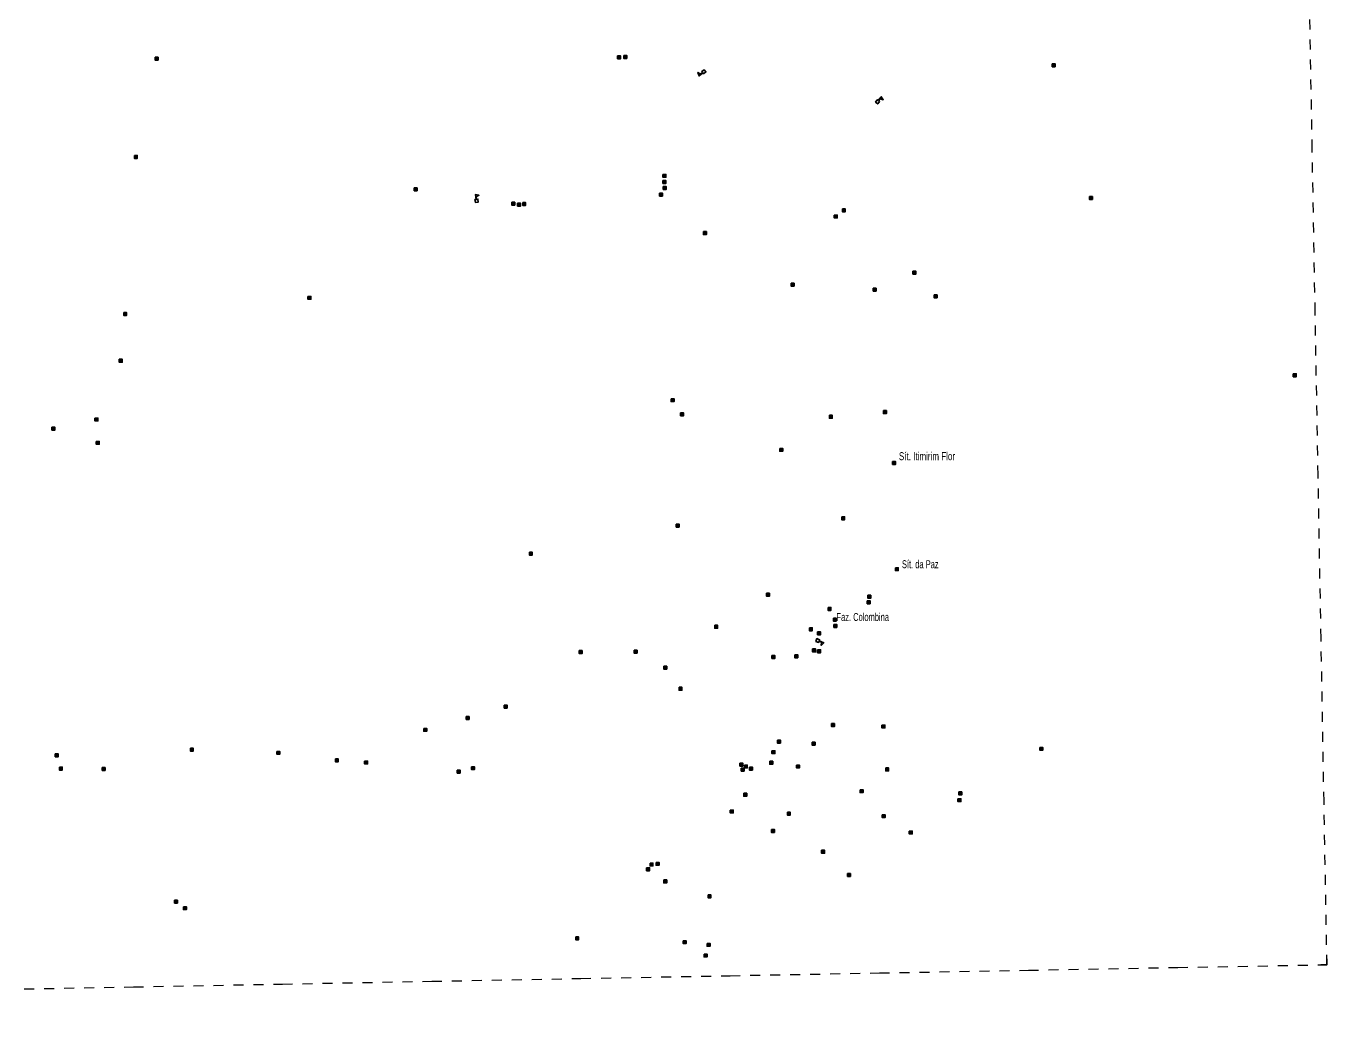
# Model space of a CAD drawing. Extents: x 220.8 to 246.7, y 7287.6 to 7315.8.
# Drawn here: x 233.65 to 246.65, y 7287.6 to 7297.47 of the extents above; entities that cross this region are included whole.
import ezdxf

# ---------------------------------------------------------------- set-up
doc = ezdxf.new("R2010")
doc.units = 0
doc.header["$LTSCALE"] = 0.032
doc.linetypes.add('SHORT_DASHED', pattern=[2.7, 1.5, -1.2])
for name, color, linetype, lineweight in [('2', 7, 'Continuous', 25), ('4', 7, 'Continuous', 25), ('58', 7, 'SHORT_DASHED', 13), ('63', 7, 'Continuous', 25)]:
    doc.layers.add(name, color=color, linetype=linetype, lineweight=lineweight)
doc.layers.add('61', color=7, linetype='Continuous')

msp = doc.modelspace()

# ---------------------------------------------------------------- hatches: boundary and pattern name
at = {"layer": '2'}
for points in [[(234.9398, 7297.1548), (234.9688, 7297.1548), (234.9688, 7297.1258), (234.9398, 7297.1258)], [(239.5615, 7297.1681), (239.5905, 7297.1681), (239.5905, 7297.1391), (239.5615, 7297.1391)], [(239.6233, 7297.1722), (239.6523, 7297.1722), (239.6523, 7297.1432), (239.6233, 7297.1432)], [(243.9053, 7297.089), (243.9343, 7297.089), (243.9343, 7297.06), (243.9053, 7297.06)], [(234.7328, 7296.1724), (234.7618, 7296.1724), (234.7618, 7296.1434), (234.7328, 7296.1434)], [(240.0151, 7295.9833), (240.0441, 7295.9833), (240.0441, 7295.9543), (240.0151, 7295.9543)], [(240.0151, 7295.9221), (240.0441, 7295.9221), (240.0441, 7295.8931), (240.0151, 7295.8931)], [(237.5286, 7295.8492), (237.5576, 7295.8492), (237.5576, 7295.8202), (237.5286, 7295.8202)], [(239.9811, 7295.7962), (240.0101, 7295.7962), (240.0101, 7295.7672), (239.9811, 7295.7672)], [(240.0183, 7295.862), (240.0473, 7295.862), (240.0473, 7295.833), (240.0183, 7295.833)], [(238.5044, 7295.7059), (238.5334, 7295.7059), (238.5334, 7295.6769), (238.5044, 7295.6769)], [(238.5624, 7295.6956), (238.5914, 7295.6956), (238.5914, 7295.6666), (238.5624, 7295.6666)], [(238.6136, 7295.7025), (238.6426, 7295.7025), (238.6426, 7295.6735), (238.6136, 7295.6735)], [(244.2773, 7295.7623), (244.3063, 7295.7623), (244.3063, 7295.7333), (244.2773, 7295.7333)], [(241.7269, 7295.5771), (241.7559, 7295.5771), (241.7559, 7295.5481), (241.7269, 7295.5481)], [(241.8083, 7295.639), (241.8373, 7295.639), (241.8373, 7295.61), (241.8083, 7295.61)], [(240.4198, 7295.4118), (240.4488, 7295.4118), (240.4488, 7295.3828), (240.4198, 7295.3828)], [(242.5135, 7295.0161), (242.5425, 7295.0161), (242.5425, 7294.9871), (242.5135, 7294.9871)], [(241.2955, 7294.8965), (241.3245, 7294.8965), (241.3245, 7294.8675), (241.2955, 7294.8675)], [(236.4668, 7294.7641), (236.4958, 7294.7641), (236.4958, 7294.7351), (236.4668, 7294.7351)], [(242.1163, 7294.8463), (242.1453, 7294.8463), (242.1453, 7294.8173), (242.1163, 7294.8173)], [(242.7249, 7294.7791), (242.7539, 7294.7791), (242.7539, 7294.7501), (242.7249, 7294.7501)], [(234.6258, 7294.6031), (234.6548, 7294.6031), (234.6548, 7294.5741), (234.6258, 7294.5741)], [(234.5814, 7294.1357), (234.6104, 7294.1357), (234.6104, 7294.1067), (234.5814, 7294.1067)], [(246.3141, 7293.9909), (246.3431, 7293.9909), (246.3431, 7293.9619), (246.3141, 7293.9619)], [(240.0965, 7293.7422), (240.1255, 7293.7422), (240.1255, 7293.7132), (240.0965, 7293.7132)], [(240.1913, 7293.6007), (240.2203, 7293.6007), (240.2203, 7293.5717), (240.1913, 7293.5717)], [(242.2183, 7293.6225), (242.2473, 7293.6225), (242.2473, 7293.5935), (242.2183, 7293.5935)], [(233.9084, 7293.4575), (233.9374, 7293.4575), (233.9374, 7293.4285), (233.9084, 7293.4285)], [(234.3386, 7293.5484), (234.3676, 7293.5484), (234.3676, 7293.5194), (234.3386, 7293.5194)], [(241.6782, 7293.5763), (241.7072, 7293.5763), (241.7072, 7293.5473), (241.6782, 7293.5473)], [(234.352, 7293.3155), (234.381, 7293.3155), (234.381, 7293.2865), (234.352, 7293.2865)], [(241.1827, 7293.2455), (241.2117, 7293.2455), (241.2117, 7293.2165), (241.1827, 7293.2165)], [(242.3099, 7293.1141), (242.3389, 7293.1141), (242.3389, 7293.0851), (242.3099, 7293.0851)], [(241.801, 7292.5617), (241.83, 7292.5617), (241.83, 7292.5327), (241.801, 7292.5327)], [(240.1468, 7292.4885), (240.1758, 7292.4885), (240.1758, 7292.4595), (240.1468, 7292.4595)], [(238.6794, 7292.2077), (238.7084, 7292.2077), (238.7084, 7292.1787), (238.6794, 7292.1787)], [(242.3372, 7292.0526), (242.3662, 7292.0526), (242.3662, 7292.0236), (242.3372, 7292.0236)], [(241.0504, 7291.7971), (241.0794, 7291.7971), (241.0794, 7291.7681), (241.0504, 7291.7681)], [(242.0629, 7291.7774), (242.0919, 7291.7774), (242.0919, 7291.7484), (242.0629, 7291.7484)], [(241.6643, 7291.656), (241.6933, 7291.656), (241.6933, 7291.627), (241.6643, 7291.627)], [(242.0563, 7291.7223), (242.0853, 7291.7223), (242.0853, 7291.6933), (242.0563, 7291.6933)], [(241.7182, 7291.5482), (241.7472, 7291.5482), (241.7472, 7291.5192), (241.7182, 7291.5192)], [(240.5318, 7291.4777), (240.5608, 7291.4777), (240.5608, 7291.4487), (240.5318, 7291.4487)], [(241.4776, 7291.4528), (241.5066, 7291.4528), (241.5066, 7291.4238), (241.4776, 7291.4238)], [(241.5606, 7291.4113), (241.5896, 7291.4113), (241.5896, 7291.3823), (241.5606, 7291.3823)], [(241.7224, 7291.486), (241.7514, 7291.486), (241.7514, 7291.457), (241.7224, 7291.457)], [(241.5108, 7291.2412), (241.5398, 7291.2412), (241.5398, 7291.2122), (241.5108, 7291.2122)], [(239.1778, 7291.2247), (239.2068, 7291.2247), (239.2068, 7291.1957), (239.1778, 7291.1957)], [(239.7265, 7291.2284), (239.7555, 7291.2284), (239.7555, 7291.1994), (239.7265, 7291.1994)], [(241.1043, 7291.1748), (241.1333, 7291.1748), (241.1333, 7291.1458), (241.1043, 7291.1458)], [(241.3324, 7291.1831), (241.3614, 7291.1831), (241.3614, 7291.1541), (241.3324, 7291.1541)], [(241.5606, 7291.2329), (241.5896, 7291.2329), (241.5896, 7291.2039), (241.5606, 7291.2039)], [(240.023, 7291.069), (240.052, 7291.069), (240.052, 7291.04), (240.023, 7291.04)], [(240.1751, 7290.8577), (240.2041, 7290.8577), (240.2041, 7290.8287), (240.1751, 7290.8287)], [(238.4279, 7290.6801), (238.4569, 7290.6801), (238.4569, 7290.6511), (238.4279, 7290.6511)], [(238.0488, 7290.5659), (238.0778, 7290.5659), (238.0778, 7290.5369), (238.0488, 7290.5369)], [(241.6991, 7290.4949), (241.7281, 7290.4949), (241.7281, 7290.4659), (241.6991, 7290.4659)], [(242.2036, 7290.4808), (242.2326, 7290.4808), (242.2326, 7290.4518), (242.2036, 7290.4518)], [(237.6247, 7290.4477), (237.6537, 7290.4477), (237.6537, 7290.4187), (237.6247, 7290.4187)], [(241.1593, 7290.33), (241.1883, 7290.33), (241.1883, 7290.301), (241.1593, 7290.301)], [(235.2916, 7290.2497), (235.3206, 7290.2497), (235.3206, 7290.2207), (235.2916, 7290.2207)], [(236.1568, 7290.2174), (236.1858, 7290.2174), (236.1858, 7290.1884), (236.1568, 7290.1884)], [(241.1038, 7290.2243), (241.1328, 7290.2243), (241.1328, 7290.1953), (241.1038, 7290.1953)], [(241.5056, 7290.3089), (241.5346, 7290.3089), (241.5346, 7290.2799), (241.5056, 7290.2799)], [(243.7815, 7290.258), (243.8105, 7290.258), (243.8105, 7290.229), (243.7815, 7290.229)], [(233.9421, 7290.193), (233.9711, 7290.193), (233.9711, 7290.164), (233.9421, 7290.164)], [(236.7412, 7290.1428), (236.7702, 7290.1428), (236.7702, 7290.1138), (236.7412, 7290.1138)], [(237.0335, 7290.1211), (237.0625, 7290.1211), (237.0625, 7290.0921), (237.0335, 7290.0921)], [(240.7839, 7290.1), (240.8129, 7290.1), (240.8129, 7290.071), (240.7839, 7290.071)], [(240.8288, 7290.0815), (240.8578, 7290.0815), (240.8578, 7290.0525), (240.8288, 7290.0525)], [(241.0826, 7290.1185), (241.1116, 7290.1185), (241.1116, 7290.0895), (241.0826, 7290.0895)], [(241.3496, 7290.0815), (241.3786, 7290.0815), (241.3786, 7290.0525), (241.3496, 7290.0525)], [(233.983, 7290.0604), (234.012, 7290.0604), (234.012, 7290.0314), (233.983, 7290.0314)], [(234.4114, 7290.0563), (234.4404, 7290.0563), (234.4404, 7290.0273), (234.4114, 7290.0273)], [(237.9589, 7290.0301), (237.9879, 7290.0301), (237.9879, 7290.0011), (237.9589, 7290.0011)], [(238.1015, 7290.0645), (238.1305, 7290.0645), (238.1305, 7290.0355), (238.1015, 7290.0355)], [(240.7971, 7290.0498), (240.8261, 7290.0498), (240.8261, 7290.0208), (240.7971, 7290.0208)], [(240.879, 7290.0604), (240.908, 7290.0604), (240.908, 7290.0314), (240.879, 7290.0314)], [(242.2404, 7290.0522), (242.2694, 7290.0522), (242.2694, 7290.0232), (242.2404, 7290.0232)], [(241.9853, 7289.8343), (242.0143, 7289.8343), (242.0143, 7289.8053), (241.9853, 7289.8053)], [(242.9721, 7289.8123), (243.0011, 7289.8123), (243.0011, 7289.7833), (242.9721, 7289.7833)], [(240.8224, 7289.7989), (240.8514, 7289.7989), (240.8514, 7289.7699), (240.8224, 7289.7699)], [(242.963, 7289.7441), (242.992, 7289.7441), (242.992, 7289.7151), (242.963, 7289.7151)], [(240.6876, 7289.631), (240.7166, 7289.631), (240.7166, 7289.602), (240.6876, 7289.602)], [(241.2577, 7289.6097), (241.2867, 7289.6097), (241.2867, 7289.5807), (241.2577, 7289.5807)], [(242.2059, 7289.5845), (242.2349, 7289.5845), (242.2349, 7289.5555), (242.2059, 7289.5555)], [(241.0992, 7289.437), (241.1282, 7289.437), (241.1282, 7289.408), (241.0992, 7289.408)], [(242.4764, 7289.4212), (242.5054, 7289.4212), (242.5054, 7289.3922), (242.4764, 7289.3922)], [(241.6006, 7289.2289), (241.6296, 7289.2289), (241.6296, 7289.1999), (241.6006, 7289.1999)], [(239.8519, 7289.0543), (239.8809, 7289.0543), (239.8809, 7289.0253), (239.8519, 7289.0253)], [(239.8857, 7289.1015), (239.9147, 7289.1015), (239.9147, 7289.0725), (239.8857, 7289.0725)], [(239.9464, 7289.1083), (239.9754, 7289.1083), (239.9754, 7289.0793), (239.9464, 7289.0793)], [(240.0229, 7288.9328), (240.0519, 7288.9328), (240.0519, 7288.9038), (240.0229, 7288.9038)], [(241.8592, 7288.9971), (241.8882, 7288.9971), (241.8882, 7288.9681), (241.8592, 7288.9681)], [(240.4656, 7288.7834), (240.4946, 7288.7834), (240.4946, 7288.7544), (240.4656, 7288.7544)], [(235.1334, 7288.7298), (235.1624, 7288.7298), (235.1624, 7288.7008), (235.1334, 7288.7008)], [(235.2229, 7288.6653), (235.2519, 7288.6653), (235.2519, 7288.6363), (235.2229, 7288.6363)], [(239.1425, 7288.3634), (239.1715, 7288.3634), (239.1715, 7288.3344), (239.1425, 7288.3344)], [(240.2172, 7288.3259), (240.2462, 7288.3259), (240.2462, 7288.2969), (240.2172, 7288.2969)], [(240.4565, 7288.2986), (240.4855, 7288.2986), (240.4855, 7288.2696), (240.4565, 7288.2696)], [(240.4262, 7288.1926), (240.4552, 7288.1926), (240.4552, 7288.1636), (240.4262, 7288.1636)]]:
    msp.add_hatch(color=256, dxfattribs=at).paths.add_polyline_path(points)

# ---------------------------------------------------------------- linework, layer by layer
for points in [[(234.9398, 7297.1548), (234.9688, 7297.1548), (234.9688, 7297.1258), (234.9398, 7297.1258)], [(239.5615, 7297.1681), (239.5905, 7297.1681), (239.5905, 7297.1391), (239.5615, 7297.1391)], [(239.6233, 7297.1722), (239.6523, 7297.1722), (239.6523, 7297.1432), (239.6233, 7297.1432)], [(243.9053, 7297.089), (243.9343, 7297.089), (243.9343, 7297.06), (243.9053, 7297.06)], [(234.7328, 7296.1724), (234.7618, 7296.1724), (234.7618, 7296.1434), (234.7328, 7296.1434)], [(240.0151, 7295.9833), (240.0441, 7295.9833), (240.0441, 7295.9543), (240.0151, 7295.9543)], [(240.0151, 7295.9221), (240.0441, 7295.9221), (240.0441, 7295.8931), (240.0151, 7295.8931)], [(237.5286, 7295.8492), (237.5576, 7295.8492), (237.5576, 7295.8202), (237.5286, 7295.8202)], [(239.9811, 7295.7962), (240.0101, 7295.7962), (240.0101, 7295.7672), (239.9811, 7295.7672)], [(240.0183, 7295.862), (240.0473, 7295.862), (240.0473, 7295.833), (240.0183, 7295.833)], [(238.5044, 7295.7059), (238.5334, 7295.7059), (238.5334, 7295.6769), (238.5044, 7295.6769)], [(238.5624, 7295.6956), (238.5914, 7295.6956), (238.5914, 7295.6666), (238.5624, 7295.6666)], [(238.6136, 7295.7025), (238.6426, 7295.7025), (238.6426, 7295.6735), (238.6136, 7295.6735)], [(244.2773, 7295.7623), (244.3063, 7295.7623), (244.3063, 7295.7333), (244.2773, 7295.7333)], [(241.7269, 7295.5771), (241.7559, 7295.5771), (241.7559, 7295.5481), (241.7269, 7295.5481)], [(241.8083, 7295.639), (241.8373, 7295.639), (241.8373, 7295.61), (241.8083, 7295.61)], [(240.4198, 7295.4118), (240.4488, 7295.4118), (240.4488, 7295.3828), (240.4198, 7295.3828)], [(242.5135, 7295.0161), (242.5425, 7295.0161), (242.5425, 7294.9871), (242.5135, 7294.9871)], [(241.2955, 7294.8965), (241.3245, 7294.8965), (241.3245, 7294.8675), (241.2955, 7294.8675)], [(236.4668, 7294.7641), (236.4958, 7294.7641), (236.4958, 7294.7351), (236.4668, 7294.7351)], [(242.1163, 7294.8463), (242.1453, 7294.8463), (242.1453, 7294.8173), (242.1163, 7294.8173)], [(242.7249, 7294.7791), (242.7539, 7294.7791), (242.7539, 7294.7501), (242.7249, 7294.7501)], [(234.6258, 7294.6031), (234.6548, 7294.6031), (234.6548, 7294.5741), (234.6258, 7294.5741)], [(234.5814, 7294.1357), (234.6104, 7294.1357), (234.6104, 7294.1067), (234.5814, 7294.1067)], [(246.3141, 7293.9909), (246.3431, 7293.9909), (246.3431, 7293.9619), (246.3141, 7293.9619)], [(240.0965, 7293.7422), (240.1255, 7293.7422), (240.1255, 7293.7132), (240.0965, 7293.7132)], [(240.1913, 7293.6007), (240.2203, 7293.6007), (240.2203, 7293.5717), (240.1913, 7293.5717)], [(242.2183, 7293.6225), (242.2473, 7293.6225), (242.2473, 7293.5935), (242.2183, 7293.5935)], [(233.9084, 7293.4575), (233.9374, 7293.4575), (233.9374, 7293.4285), (233.9084, 7293.4285)], [(234.3386, 7293.5484), (234.3676, 7293.5484), (234.3676, 7293.5194), (234.3386, 7293.5194)], [(241.6782, 7293.5763), (241.7072, 7293.5763), (241.7072, 7293.5473), (241.6782, 7293.5473)], [(234.352, 7293.3155), (234.381, 7293.3155), (234.381, 7293.2865), (234.352, 7293.2865)], [(241.1827, 7293.2455), (241.2117, 7293.2455), (241.2117, 7293.2165), (241.1827, 7293.2165)], [(242.3099, 7293.1141), (242.3389, 7293.1141), (242.3389, 7293.0851), (242.3099, 7293.0851)], [(241.801, 7292.5617), (241.83, 7292.5617), (241.83, 7292.5327), (241.801, 7292.5327)], [(240.1468, 7292.4885), (240.1758, 7292.4885), (240.1758, 7292.4595), (240.1468, 7292.4595)], [(238.6794, 7292.2077), (238.7084, 7292.2077), (238.7084, 7292.1787), (238.6794, 7292.1787)], [(242.3372, 7292.0526), (242.3662, 7292.0526), (242.3662, 7292.0236), (242.3372, 7292.0236)], [(241.0504, 7291.7971), (241.0794, 7291.7971), (241.0794, 7291.7681), (241.0504, 7291.7681)], [(242.0629, 7291.7774), (242.0919, 7291.7774), (242.0919, 7291.7484), (242.0629, 7291.7484)], [(241.6643, 7291.656), (241.6933, 7291.656), (241.6933, 7291.627), (241.6643, 7291.627)], [(242.0563, 7291.7223), (242.0853, 7291.7223), (242.0853, 7291.6933), (242.0563, 7291.6933)], [(241.7182, 7291.5482), (241.7472, 7291.5482), (241.7472, 7291.5192), (241.7182, 7291.5192)], [(240.5318, 7291.4777), (240.5608, 7291.4777), (240.5608, 7291.4487), (240.5318, 7291.4487)], [(241.4776, 7291.4528), (241.5066, 7291.4528), (241.5066, 7291.4238), (241.4776, 7291.4238)], [(241.5606, 7291.4113), (241.5896, 7291.4113), (241.5896, 7291.3823), (241.5606, 7291.3823)], [(241.7224, 7291.486), (241.7514, 7291.486), (241.7514, 7291.457), (241.7224, 7291.457)], [(241.5108, 7291.2412), (241.5398, 7291.2412), (241.5398, 7291.2122), (241.5108, 7291.2122)], [(239.1778, 7291.2247), (239.2068, 7291.2247), (239.2068, 7291.1957), (239.1778, 7291.1957)], [(239.7265, 7291.2284), (239.7555, 7291.2284), (239.7555, 7291.1994), (239.7265, 7291.1994)], [(241.1043, 7291.1748), (241.1333, 7291.1748), (241.1333, 7291.1458), (241.1043, 7291.1458)], [(241.3324, 7291.1831), (241.3614, 7291.1831), (241.3614, 7291.1541), (241.3324, 7291.1541)], [(241.5606, 7291.2329), (241.5896, 7291.2329), (241.5896, 7291.2039), (241.5606, 7291.2039)], [(240.023, 7291.069), (240.052, 7291.069), (240.052, 7291.04), (240.023, 7291.04)], [(240.1751, 7290.8577), (240.2041, 7290.8577), (240.2041, 7290.8287), (240.1751, 7290.8287)], [(238.4279, 7290.6801), (238.4569, 7290.6801), (238.4569, 7290.6511), (238.4279, 7290.6511)], [(238.0488, 7290.5659), (238.0778, 7290.5659), (238.0778, 7290.5369), (238.0488, 7290.5369)], [(241.6991, 7290.4949), (241.7281, 7290.4949), (241.7281, 7290.4659), (241.6991, 7290.4659)], [(242.2036, 7290.4808), (242.2326, 7290.4808), (242.2326, 7290.4518), (242.2036, 7290.4518)], [(237.6247, 7290.4477), (237.6537, 7290.4477), (237.6537, 7290.4187), (237.6247, 7290.4187)], [(241.1593, 7290.33), (241.1883, 7290.33), (241.1883, 7290.301), (241.1593, 7290.301)], [(235.2916, 7290.2497), (235.3206, 7290.2497), (235.3206, 7290.2207), (235.2916, 7290.2207)], [(236.1568, 7290.2174), (236.1858, 7290.2174), (236.1858, 7290.1884), (236.1568, 7290.1884)], [(241.1038, 7290.2243), (241.1328, 7290.2243), (241.1328, 7290.1953), (241.1038, 7290.1953)], [(241.5056, 7290.3089), (241.5346, 7290.3089), (241.5346, 7290.2799), (241.5056, 7290.2799)], [(243.7815, 7290.258), (243.8105, 7290.258), (243.8105, 7290.229), (243.7815, 7290.229)], [(233.9421, 7290.193), (233.9711, 7290.193), (233.9711, 7290.164), (233.9421, 7290.164)], [(236.7412, 7290.1428), (236.7702, 7290.1428), (236.7702, 7290.1138), (236.7412, 7290.1138)], [(237.0335, 7290.1211), (237.0625, 7290.1211), (237.0625, 7290.0921), (237.0335, 7290.0921)], [(240.7839, 7290.1), (240.8129, 7290.1), (240.8129, 7290.071), (240.7839, 7290.071)], [(240.8288, 7290.0815), (240.8578, 7290.0815), (240.8578, 7290.0525), (240.8288, 7290.0525)], [(241.0826, 7290.1185), (241.1116, 7290.1185), (241.1116, 7290.0895), (241.0826, 7290.0895)], [(241.3496, 7290.0815), (241.3786, 7290.0815), (241.3786, 7290.0525), (241.3496, 7290.0525)], [(233.983, 7290.0604), (234.012, 7290.0604), (234.012, 7290.0314), (233.983, 7290.0314)], [(234.4114, 7290.0563), (234.4404, 7290.0563), (234.4404, 7290.0273), (234.4114, 7290.0273)], [(237.9589, 7290.0301), (237.9879, 7290.0301), (237.9879, 7290.0011), (237.9589, 7290.0011)], [(238.1015, 7290.0645), (238.1305, 7290.0645), (238.1305, 7290.0355), (238.1015, 7290.0355)], [(240.7971, 7290.0498), (240.8261, 7290.0498), (240.8261, 7290.0208), (240.7971, 7290.0208)], [(240.879, 7290.0604), (240.908, 7290.0604), (240.908, 7290.0314), (240.879, 7290.0314)], [(242.2404, 7290.0522), (242.2694, 7290.0522), (242.2694, 7290.0232), (242.2404, 7290.0232)], [(241.9853, 7289.8343), (242.0143, 7289.8343), (242.0143, 7289.8053), (241.9853, 7289.8053)], [(242.9721, 7289.8123), (243.0011, 7289.8123), (243.0011, 7289.7833), (242.9721, 7289.7833)], [(240.8224, 7289.7989), (240.8514, 7289.7989), (240.8514, 7289.7699), (240.8224, 7289.7699)], [(242.963, 7289.7441), (242.992, 7289.7441), (242.992, 7289.7151), (242.963, 7289.7151)], [(240.6876, 7289.631), (240.7166, 7289.631), (240.7166, 7289.602), (240.6876, 7289.602)], [(241.2577, 7289.6097), (241.2867, 7289.6097), (241.2867, 7289.5807), (241.2577, 7289.5807)], [(242.2059, 7289.5845), (242.2349, 7289.5845), (242.2349, 7289.5555), (242.2059, 7289.5555)], [(241.0992, 7289.437), (241.1282, 7289.437), (241.1282, 7289.408), (241.0992, 7289.408)], [(242.4764, 7289.4212), (242.5054, 7289.4212), (242.5054, 7289.3922), (242.4764, 7289.3922)], [(241.6006, 7289.2289), (241.6296, 7289.2289), (241.6296, 7289.1999), (241.6006, 7289.1999)], [(239.8519, 7289.0543), (239.8809, 7289.0543), (239.8809, 7289.0253), (239.8519, 7289.0253)], [(239.8857, 7289.1015), (239.9147, 7289.1015), (239.9147, 7289.0725), (239.8857, 7289.0725)], [(239.9464, 7289.1083), (239.9754, 7289.1083), (239.9754, 7289.0793), (239.9464, 7289.0793)], [(240.0229, 7288.9328), (240.0519, 7288.9328), (240.0519, 7288.9038), (240.0229, 7288.9038)], [(241.8592, 7288.9971), (241.8882, 7288.9971), (241.8882, 7288.9681), (241.8592, 7288.9681)], [(240.4656, 7288.7834), (240.4946, 7288.7834), (240.4946, 7288.7544), (240.4656, 7288.7544)], [(235.1334, 7288.7298), (235.1624, 7288.7298), (235.1624, 7288.7008), (235.1334, 7288.7008)], [(235.2229, 7288.6653), (235.2519, 7288.6653), (235.2519, 7288.6363), (235.2229, 7288.6363)], [(239.1425, 7288.3634), (239.1715, 7288.3634), (239.1715, 7288.3344), (239.1425, 7288.3344)], [(240.2172, 7288.3259), (240.2462, 7288.3259), (240.2462, 7288.2969), (240.2172, 7288.2969)], [(240.4565, 7288.2986), (240.4855, 7288.2986), (240.4855, 7288.2696), (240.4565, 7288.2696)], [(240.4262, 7288.1926), (240.4552, 7288.1926), (240.4552, 7288.1636), (240.4262, 7288.1636)]]:
    msp.add_lwpolyline(points, close=True, dxfattribs=at)
at = {"layer": '4'}
for points in [[(240.414, 7296.9985), (240.3762, 7296.9682), (240.3641, 7297.002), (240.3905, 7296.986), (240.4109, 7297.0023)], [(240.4109, 7297.0023), (240.4034, 7297.0118), (240.426, 7297.0299), (240.4441, 7297.0073), (240.4214, 7296.9892), (240.414, 7296.9985)], [(242.1701, 7296.7185), (242.1796, 7296.711), (242.1618, 7296.6882), (242.1389, 7296.706), (242.1569, 7296.7288), (242.1662, 7296.7215)], [(242.1662, 7296.7215), (242.196, 7296.7597), (242.2156, 7296.7296), (242.1862, 7296.7391), (242.1701, 7296.7185)], [(238.1528, 7295.7341), (238.1648, 7295.736), (238.1694, 7295.7074), (238.1408, 7295.7027), (238.1362, 7295.7313), (238.148, 7295.7333)], [(238.148, 7295.7333), (238.1402, 7295.781), (238.1755, 7295.775), (238.1486, 7295.7598), (238.1528, 7295.7341)], [(241.5743, 7291.3175), (241.5698, 7291.3064), (241.5429, 7291.3173), (241.5539, 7291.3442), (241.5807, 7291.3332), (241.5762, 7291.322)], [(241.5762, 7291.322), (241.621, 7291.3038), (241.5974, 7291.2768), (241.5985, 7291.3077), (241.5743, 7291.3175)]]:
    msp.add_lwpolyline(points, dxfattribs=at)
at = {"layer": '58'}
for points in [[(246.6507, 7288.0853), (246.6212, 7289.7146), (246.5917, 7291.3439), (246.5622, 7292.9732), (246.5328, 7294.6024), (246.5034, 7296.2317), (246.4739, 7297.861), (246.4446, 7299.4903), (246.4152, 7301.1196), (246.3858, 7302.7489), (246.3565, 7304.3782), (246.3272, 7306.0075), (246.2979, 7307.6367), (246.2685, 7309.266), (246.2393, 7310.8953), (246.21, 7312.5246), (246.1808, 7314.1539), (246.1516, 7315.7832)], [(221.3035, 7287.6034), (222.7945, 7287.633), (224.2855, 7287.6625), (225.7765, 7287.6918), (227.2675, 7287.7209), (228.7585, 7287.7499), (230.2495, 7287.7787), (231.7405, 7287.8074), (233.2315, 7287.836), (234.7225, 7287.8643), (236.2135, 7287.8925), (237.7045, 7287.9205), (239.1956, 7287.9483), (240.6866, 7287.9761), (242.1776, 7288.0036), (243.6686, 7288.031), (245.1597, 7288.0583), (246.6507, 7288.0853)]]:
    msp.add_lwpolyline(points, dxfattribs=at)
at = {"layer": '63'}
msp.add_lwpolyline([(246.5891, 7288.0853), (246.6507, 7288.0853), (246.6507, 7288.146)], dxfattribs=at)

# ---------------------------------------------------------------- texts
at = {"layer": '61'}
for s, width, p in [('Sít. Itimirim Flor', 0.75, (242.3726, 7293.1277)), ('Sít. da Paz', 0.7, (242.4029, 7292.0479)), ('Faz. Colombina', 0.7, (241.7491, 7291.5206))]:
    msp.add_text(s, height=0.08, dxfattribs=dict(at, width=width)).set_placement(p)

doc.saveas('drawing.dxf')
